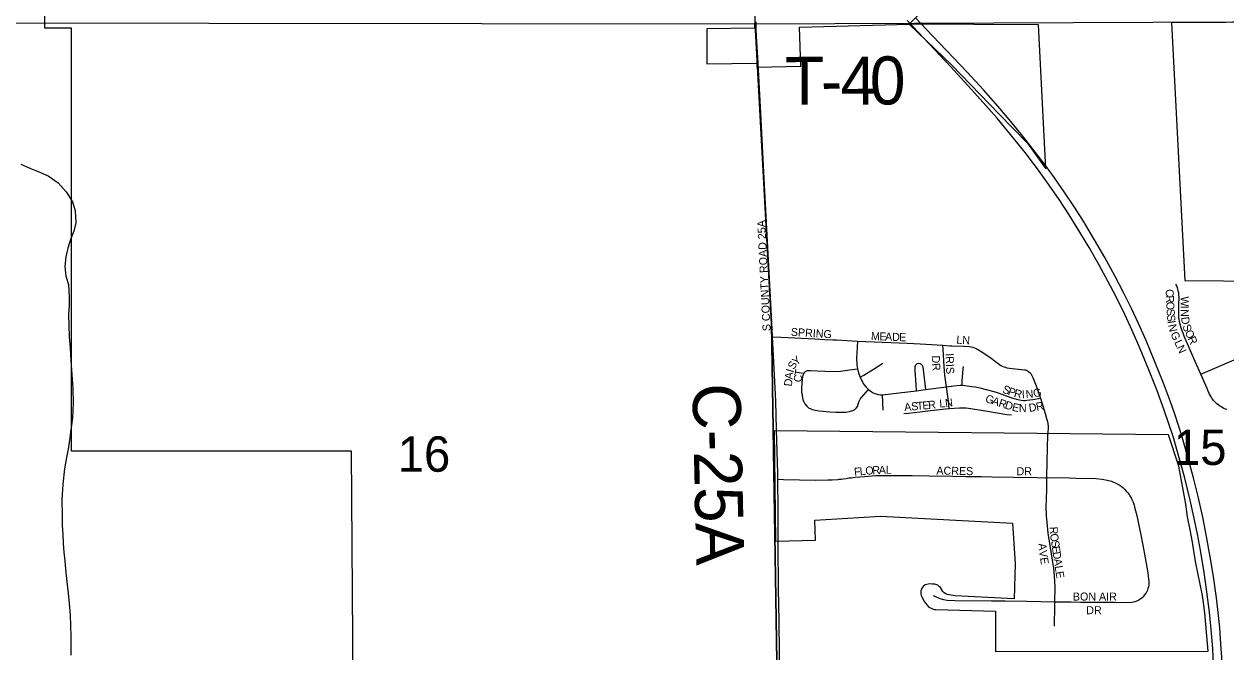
# Model space of a CAD drawing. Extents: x 0 to 680, y 0 to 440.
# Drawn here: x 474.22 to 499.3, y 246.29 to 259.39 of the extents above; entities that cross this region are included whole.
import ezdxf

# ---------------------------------------------------------------- set-up
doc = ezdxf.new("R2010")
doc.units = 0
for name, color, linetype in [('GM_X_City_Street', 7, 'Continuous'), ('GM_X_City_Street_Text', 7, 'Continuous'), ('GM_X_Corporation', 7, 'Continuous'), ('GM_X_County_Road', 7, 'Continuous'), ('GM_X_County_Road_Text', 7, 'Continuous'), ('GM_X_Interstate_Route', 7, 'Continuous'), ('GM_X_Minor_River', 7, 'Continuous'), ('GM_X_Section', 7, 'Continuous'), ('GM_X_Section_Text', 7, 'Continuous'), ('GM_X_Township_Road_Text', 7, 'Continuous'), ('GM_X_Township_Subdivision', 7, 'Continuous'), ('GM_X_Township_Subdivision_Text', 7, 'Continuous')]:
    doc.layers.add(name, color=color, linetype=linetype)

msp = doc.modelspace()

# ---------------------------------------------------------------- linework, layer by layer
at = {"layer": 'GM_X_City_Street'}
for points in [[(489.837, 252.862), (489.82, 253.168), (489.72, 255.118), (489.658, 256.301), (489.6, 257.393), (489.536, 258.572)], [(498.769, 252.09), (498.627, 252.416), (498.427, 252.881), (498.403, 252.94), (498.383, 252.992), (498.368, 253.035), (498.355, 253.075), (498.345, 253.11), (498.334, 253.15), (498.326, 253.192), (498.32, 253.233), (498.314, 253.27), (498.311, 253.314), (498.31, 253.361), (498.31, 253.412), (498.313, 253.536), (498.317, 253.693), (498.314, 253.741), (498.309, 253.78), (498.301, 253.819), (498.293, 253.856), (498.283, 253.888), (498.268, 253.927), (498.251, 253.963)], [(489.837, 252.862), (490.008, 252.859), (490.161, 252.854), (490.303, 252.847), (490.718, 252.825), (490.925, 252.811), (491.098, 252.804), (491.17, 252.801), (491.61, 252.772)], [(489.922, 250.933), (489.903, 251.521), (489.865, 252.334), (489.837, 252.862)], [(491.61, 252.772), (491.602, 252.645), (491.592, 252.421), (491.597, 252.29), (491.609, 252.199)], [(491.61, 252.772), (492.304, 252.748), (492.654, 252.735), (492.916, 252.717), (493.393, 252.689)], [(493.467, 251.825), (493.434, 252.063), (493.414, 252.247), (493.397, 252.605), (493.393, 252.689)], [(493.393, 252.689), (493.538, 252.68), (493.579, 252.679), (493.828, 252.674), (493.946, 252.666), (494.018, 252.65), (494.086, 252.622), (494.169, 252.573), (494.369, 252.439), (494.517, 252.327), (494.6, 252.27), (494.63, 252.255), (494.662, 252.241), (494.694, 252.23), (494.727, 252.222), (494.835, 252.203), (494.97, 252.189), (495.03, 252.186), (495.091, 252.179), (495.115, 252.174), (495.137, 252.168), (495.157, 252.158), (495.18, 252.143), (495.21, 252.117), (495.224, 252.102), (495.24, 252.075), (495.268, 252.018), (495.334, 251.845), (495.424, 251.587)], [(498.769, 252.09), (499.158, 252.253), (499.369, 252.343), (499.685, 252.479)], [(491.667, 252.022), (491.741, 252.066), (491.944, 252.193), (492.138, 252.313)], [(492.839, 251.739), (492.831, 251.866), (492.812, 252.172), (492.815, 252.249), (492.825, 252.28), (492.848, 252.303), (492.879, 252.314), (492.911, 252.312), (492.941, 252.298), (492.962, 252.274), (492.974, 252.243), (493.03, 251.768)], [(493.793, 251.854), (493.796, 251.944), (493.814, 252.195), (493.82, 252.25)], [(490.45, 251.688), (490.45, 251.795), (490.462, 251.979), (490.474, 252.063), (490.488, 252.1), (490.511, 252.131), (490.534, 252.148), (490.55, 252.155), (490.569, 252.16), (490.632, 252.162), (490.925, 252.147), (491.112, 252.142), (491.255, 252.151), (491.498, 252.184), (491.609, 252.199)], [(491.609, 252.199), (491.617, 252.16), (491.638, 252.096), (491.667, 252.022)], [(491.667, 252.022), (491.693, 251.965), (491.713, 251.925), (491.73, 251.895), (491.752, 251.862), (491.788, 251.815), (491.839, 251.766)], [(499.313, 251.347), (499.286, 251.358), (499.251, 251.374), (499.216, 251.392), (499.188, 251.409), (499.158, 251.428), (499.134, 251.447), (499.105, 251.469), (499.081, 251.491), (499.057, 251.516), (499.039, 251.538), (499.021, 251.56), (499.002, 251.587), (498.984, 251.616), (498.964, 251.65), (498.946, 251.684), (498.924, 251.729), (498.9, 251.785), (498.769, 252.09)], [(490.45, 251.688), (490.454, 251.644), (490.462, 251.594), (490.47, 251.559), (490.483, 251.523), (490.512, 251.468), (490.551, 251.419), (490.59, 251.387), (490.636, 251.366), (490.673, 251.352), (490.729, 251.337), (490.813, 251.322), (491.03, 251.298), (491.159, 251.293), (491.366, 251.296), (491.44, 251.307), (491.51, 251.328), (491.555, 251.353), (491.585, 251.379), (491.608, 251.412), (491.626, 251.459), (491.646, 251.523), (491.665, 251.565), (491.693, 251.603), (491.839, 251.766)], [(491.839, 251.766), (491.895, 251.726), (491.939, 251.7), (491.974, 251.684), (492, 251.674), (492.04, 251.664), (492.086, 251.659), (492.131, 251.656)], [(492.131, 251.656), (492.532, 251.703), (492.839, 251.739)], [(492.839, 251.739), (493.03, 251.768)], [(493.03, 251.768), (493.467, 251.825)], [(493.467, 251.825), (493.621, 251.845), (493.752, 251.856), (493.793, 251.854)], [(493.523, 251.371), (493.506, 251.533), (493.497, 251.62), (493.467, 251.825)], [(493.793, 251.854), (493.85, 251.85), (493.996, 251.832), (494.069, 251.82), (494.162, 251.799), (494.297, 251.766), (494.454, 251.722), (494.522, 251.703), (494.621, 251.67), (494.713, 251.638), (494.852, 251.588), (494.956, 251.555), (495.023, 251.542), (495.075, 251.537), (495.109, 251.538), (495.141, 251.542), (495.264, 251.559), (495.424, 251.587)], [(492.147, 251.339), (492.131, 251.656)], [(495.424, 251.587), (495.452, 251.495), (495.525, 251.269), (495.554, 251.165), (495.57, 251.101), (495.579, 251.049), (495.584, 250.999), (495.579, 250.836)], [(492.575, 251.263), (492.673, 251.271), (492.911, 251.299), (493.129, 251.326), (493.509, 251.37), (493.523, 251.371)], [(493.523, 251.371), (493.74, 251.386), (493.873, 251.384), (494.015, 251.367), (494.318, 251.314), (494.726, 251.243), (494.821, 251.236)], [(490.003, 243.711), (490.003, 243.935), (489.987, 245.238), (489.98, 246.289), (489.973, 246.935), (489.963, 247.614), (489.958, 248.547)]]:
    msp.add_lwpolyline(points, dxfattribs=at)
at = {"layer": 'GM_X_Corporation'}
for points in [[(481.118, 241.691), (481.055, 250.48), (475.217, 250.48), (475.216, 259.303), (474.655, 259.303), (474.655, 261.138), (474.551, 261.138), (474.551, 261.872), (474.184, 261.872)], [(489.496, 260.373), (489.458, 259.301), (488.464, 259.286), (488.464, 258.56), (489.507, 258.575), (489.51, 258.492), (490.429, 258.511), (490.397, 259.325), (492.69, 259.383), (492.991, 259.695)], [(502.694, 259.441), (498.159, 259.415), (498.441, 254.039), (503.27, 254.001)]]:
    msp.add_lwpolyline(points, dxfattribs=at)
for points in [[(492.69, 259.383), (493.577, 258.528), (494.561, 257.519), (495.158, 256.906), (495.541, 256.372), (495.384, 259.371)], [(489.872, 250.903), (489.897, 248.605), (490.732, 248.624), (490.722, 249.041), (491.638, 249.094), (492.092, 249.122), (494.842, 248.977), (494.901, 248.138), (494.875, 247.398), (493.648, 247.462), (493.481, 247.492), (493.449, 247.502), (493.416, 247.524), (493.388, 247.554), (493.338, 247.635), (493.314, 247.661), (493.282, 247.685), (493.22, 247.704), (493.164, 247.71), (493.124, 247.713), (493.083, 247.71), (493.021, 247.691), (492.98, 247.66), (492.958, 247.629), (492.941, 247.595), (492.934, 247.56), (492.931, 247.515), (492.94, 247.473), (492.959, 247.432), (493.006, 247.342), (493.031, 247.308), (493.099, 247.23), (493.207, 247.181), (493.241, 247.18), (494.486, 247.141), (494.486, 246.305), (498.922, 246.307), (498.855, 247.107), (498.804, 247.469), (498.663, 248.18), (498.596, 248.582), (498.552, 248.839), (498.492, 249.113), (498.455, 249.374), (498.315, 250.17), (498.1, 250.822)]]:
    msp.add_lwpolyline(points, close=True, dxfattribs=at)
at = {"layer": 'GM_X_County_Road'}
for points in [[(489.536, 258.572), (489.517, 258.911), (489.505, 259.127), (489.498, 259.298), (489.498, 259.365), (489.498, 259.435)], [(489.946, 249.896), (489.945, 250.021), (489.922, 250.933)], [(489.958, 248.547), (489.953, 249.249), (489.946, 249.896)]]:
    msp.add_lwpolyline(points, dxfattribs=at)
at = {"layer": 'GM_X_Interstate_Route'}
for points in [[(496.342, 255.24), (496.133, 255.567), (495.922, 255.886), (495.716, 256.182), (495.536, 256.43), (495.325, 256.708), (495.028, 257.087), (494.739, 257.443), (494.498, 257.726), (494.236, 258.019), (493.894, 258.388), (493.184, 259.133), (492.811, 259.528)], [(499.057, 245.417), (499.021, 246.364), (498.984, 246.764), (498.949, 247.125), (498.896, 247.549), (498.839, 247.951), (498.763, 248.416), (498.701, 248.75), (498.64, 249.051), (498.549, 249.458), (498.438, 249.916), (498.35, 250.244), (498.194, 250.787), (498.006, 251.337), (497.851, 251.759), (497.689, 252.178), (497.509, 252.614), (497.341, 252.995), (497.183, 253.333), (497.004, 253.698), (496.833, 254.029), (496.645, 254.376), (496.442, 254.728), (496.25, 255.047), (496.024, 255.41), (495.814, 255.731), (495.609, 256.03), (495.366, 256.368), (495.108, 256.709), (494.526, 257.423), (494.053, 257.956), (493.556, 258.496), (492.643, 259.46)], [(498.382, 250.782), (498.228, 251.252), (498.138, 251.511), (497.992, 251.899), (497.814, 252.346), (497.628, 252.79), (497.474, 253.14), (497.325, 253.456), (497.164, 253.779), (496.977, 254.137), (496.767, 254.521), (496.554, 254.89), (496.35, 255.226), (496.342, 255.24)], [(499.197, 246.357), (499.165, 246.795), (499.14, 247.056), (499.097, 247.425), (499.034, 247.869), (498.969, 248.279), (498.893, 248.699), (498.811, 249.106), (498.715, 249.533), (498.618, 249.925), (498.53, 250.252), (498.382, 250.782)], [(499.251, 215.048), (499.251, 215.074), (499.251, 217.418), (499.248, 220.255), (499.248, 224.759), (499.245, 229.732), (499.245, 230.699), (499.235, 234.233), (499.236, 234.641), (499.237, 236.207), (499.231, 238.398), (499.236, 241.137), (499.239, 243.03), (499.243, 244.793), (499.238, 245.307), (499.227, 245.734), (499.207, 246.182), (499.197, 246.357)]]:
    msp.add_lwpolyline(points, dxfattribs=at)
at = {"layer": 'GM_X_Minor_River'}
msp.add_lwpolyline([(474.156, 256.468), (474.348, 256.385), (474.521, 256.316), (474.727, 256.22), (474.933, 256.077), (475.104, 255.888), (475.236, 255.679), (475.294, 255.491), (475.304, 255.244), (475.262, 255.07), (475.193, 254.897), (475.138, 254.717), (475.095, 254.537), (475.073, 254.33), (475.097, 254.129), (475.149, 253.955), (475.166, 253.694), (475.164, 253.52), (475.155, 253.333), (475.159, 253.099), (475.169, 252.864), (475.187, 252.63), (475.197, 252.369), (475.22, 252.081), (475.243, 251.787), (475.247, 251.479), (475.236, 251.178), (475.2, 250.924), (475.171, 250.711), (475.142, 250.524), (475.113, 250.35), (475.07, 250.11), (475.033, 249.796), (475.016, 249.475), (475.019, 249.141), (475.023, 248.934), (475.034, 248.746), (475.038, 248.552), (475.056, 248.371), (475.074, 248.197), (475.086, 248.017), (475.116, 247.755), (475.147, 247.521), (475.164, 247.307), (475.188, 247.059), (475.192, 246.838), (475.203, 246.617), (475.201, 246.437), (475.198, 246.223)], dxfattribs=at)
at = {"layer": 'GM_X_Section'}
for points in [[(489.476, 259.394), (489.813, 253.134), (489.987, 242.13), (472.319, 241.773), (472.369, 259.414)], [(507.727, 259.473), (507.628, 241.733), (499.118, 242.119), (489.987, 242.13), (489.813, 253.134), (489.476, 259.394)]]:
    msp.add_lwpolyline(points, close=True, dxfattribs=at)
at = {"layer": 'GM_X_Township_Subdivision'}
for points in [[(495.559, 249.928), (495.564, 250.276), (495.57, 250.536), (495.579, 250.836)], [(489.946, 249.896), (490.064, 249.893), (490.731, 249.876), (490.988, 249.881), (491.084, 249.886), (491.206, 249.893), (491.228, 249.895), (491.266, 249.9), (491.309, 249.905), (491.371, 249.914), (491.429, 249.922), (491.482, 249.928), (491.563, 249.938), (491.753, 249.955), (491.837, 249.962), (491.995, 249.97), (492.105, 249.972), (492.321, 249.971), (492.747, 249.972), (493.107, 249.968), (493.599, 249.956), (493.871, 249.954), (493.97, 249.953), (494.188, 249.949), (494.418, 249.947), (494.866, 249.936), (495.347, 249.93), (495.53, 249.928), (495.559, 249.928)], [(495.729, 247.341), (495.73, 247.642), (495.72, 247.882), (495.705, 248.035), (495.657, 248.337), (495.587, 248.769), (495.557, 249.067), (495.552, 249.123), (495.546, 249.34), (495.549, 249.455), (495.557, 249.717), (495.558, 249.859), (495.559, 249.928)], [(495.559, 249.928), (495.716, 249.929), (496.033, 249.923), (496.164, 249.919), (496.579, 249.909), (496.711, 249.898), (496.821, 249.879), (496.907, 249.855), (496.999, 249.816), (497.068, 249.776), (497.107, 249.748), (497.142, 249.72), (497.178, 249.688), (497.214, 249.65), (497.247, 249.612), (497.274, 249.574), (497.292, 249.548), (497.322, 249.496), (497.333, 249.476), (497.348, 249.443), (497.359, 249.415), (497.38, 249.352), (497.398, 249.286), (497.434, 249.139), (497.475, 248.931), (497.51, 248.774), (497.561, 248.522), (497.612, 248.254), (497.648, 248.059), (497.667, 247.94), (497.676, 247.871), (497.68, 247.821), (497.684, 247.757), (497.684, 247.694), (497.678, 247.651), (497.669, 247.614), (497.65, 247.561)], [(493.187, 247.469), (493.328, 247.407), (493.403, 247.385), (493.48, 247.373), (493.645, 247.367), (494.404, 247.36)], [(495.729, 247.341), (496.064, 247.337), (496.26, 247.334), (496.796, 247.33), (496.97, 247.329), (497.223, 247.325), (497.334, 247.332), (497.401, 247.345), (497.455, 247.365), (497.502, 247.393), (497.549, 247.427), (497.579, 247.457), (497.603, 247.487), (497.63, 247.522), (497.65, 247.561)], [(494.404, 247.36), (494.432, 247.359), (494.605, 247.357), (494.69, 247.357)], [(494.69, 247.357), (495.136, 247.349), (495.729, 247.341)], [(495.722, 246.832), (495.728, 247.259), (495.729, 247.341)]]:
    msp.add_lwpolyline(points, dxfattribs=at)

# ---------------------------------------------------------------- texts
at = {"layer": 'GM_X_City_Street_Text'}
for s, height, rotation, p in [('S COUNTY ROAD 25A', 0.16689, 92.883, (489.799, 252.987)), ('C', 0.167, 272.7945, (498.035, 253.857)), ('R', 0.167, 272.8081, (498.041, 253.725)), ('O', 0.167, 272.9019, (498.048, 253.593)), ('W', 0.167, 270.4539, (498.351, 253.708)), ('I', 0.167, 270.437, (498.353, 253.517)), ('S', 0.167, 273.7803, (498.056, 253.443)), ('S', 0.167, 275.2323, (498.064, 253.321)), ('N', 0.167, 270.4545, (498.353, 253.443)), ('D', 0.167, 278.8202, (498.357, 253.27)), ('SPRING', 0.1669, 356.4925, (490.215, 252.887)), ('I', 0.167, 279.3977, (498.076, 253.191)), ('N', 0.167, 281.6422, (498.089, 253.112)), ('G', 0.167, 294.9637, (498.132, 252.928)), ('S', 0.167, 288.473, (498.386, 253.095)), ('O', 0.167, 295.1802, (498.432, 252.964)), ('M', 0.167, 357.8506, (491.888, 252.799)), ('E', 0.167, 357.8415, (492.064, 252.793)), ('A', 0.167, 357.8424, (492.182, 252.788)), ('D', 0.167, 357.8535, (492.329, 252.783)), ('E', 0.167, 357.8415, (492.475, 252.777)), ('L', 0.167, 355.4609, (493.667, 252.726)), ('N', 0.167, 358.1706, (493.793, 252.716)), ('L', 0.167, 294.5367, (498.213, 252.755)), ('R', 0.167, 294.4359, (498.494, 252.831)), ('Y', 0.167, 39.4278, (490.334, 252.26)), ('IRIS', 0.1669, 272.2013, (493.446, 252.52)), ('N', 0.167, 294.4729, (498.261, 252.648)), ('S', 0.167, 59.7298, (490.285, 252.17)), ('D', 0.167, 270.2186, (493.162, 252.474)), ('R', 0.167, 275.9335, (493.163, 252.309)), ('D', 0.167, 84.3525, (490.24, 251.826)), ('A', 0.167, 84.3525, (490.254, 251.972)), ('I', 0.167, 72.7816, (490.267, 252.109)), ('C', 0.167, 81.5197, (490.438, 251.908)), ('T', 0.167, 79.6438, (490.457, 252.037)), ('S', 0.167, 337.605, (494.617, 251.71)), ('P', 0.167, 340.2765, (494.734, 251.662)), ('R', 0.167, 346.4363, (494.863, 251.617)), ('I', 0.167, 1.8864, (495.04, 251.581)), ('N', 0.167, 5.4829, (495.125, 251.584)), ('G', 0.167, 11.3063, (495.289, 251.601)), ('A', 0.167, 4.7491, (492.59, 251.316)), ('S', 0.167, 4.7691, (492.736, 251.328)), ('T', 0.167, 4.7319, (492.853, 251.338)), ('E', 0.167, 4.7691, (492.97, 251.348)), ('R', 0.167, 6.7104, (493.093, 251.358)), ('L', 0.167, 5.0881, (493.324, 251.389)), ('N', 0.167, 6.6489, (493.446, 251.4)), ('G', 0.167, 341.5167, (494.261, 251.511)), ('A', 0.167, 341.5167, (494.4, 251.465)), ('R', 0.167, 341.5755, (494.54, 251.418)), ('D', 0.167, 343.0182, (494.67, 251.375)), ('E', 0.167, 346.2711, (494.82, 251.329)), ('D', 0.167, 8.1226, (495.194, 251.299)), ('R', 0.167, 11.5544, (495.35, 251.321)), ('N', 0.167, 359.2945, (494.975, 251.296))]:
    msp.add_text(s, height=height, rotation=rotation, dxfattribs=at).set_placement(p)
at = {"layer": 'GM_X_County_Road_Text'}
msp.add_text('C-25A', height=1.0014, rotation=271.2667, dxfattribs=at).set_placement((488.165, 251.886))
at = {"layer": 'GM_X_Section_Text'}
for s, p in [('16', (482.018, 250.052)), ('15', (498.21, 250.193))]:
    msp.add_text(s, height=0.7377, rotation=0, dxfattribs=at).set_placement(p)
at = {"layer": 'GM_X_Township_Road_Text'}
for s, rotation, p in [('T', 0.3831, (490.102, 257.702)), ('4', 0.1604, (491.257, 257.709)), ('0', 0.1604, (491.868, 257.711)), ('-', 0.3188, (490.85, 257.707))]:
    msp.add_text(s, height=1.001, rotation=rotation, dxfattribs=at).set_placement(p)
at = {"layer": 'GM_X_Township_Subdivision_Text'}
for s, height, rotation, p in [('F', 0.167, 5.6644, (491.546, 249.965)), ('L', 0.167, 5.6644, (491.663, 249.976)), ('O', 0.167, 4.2009, (491.779, 249.988)), ('R', 0.167, 2.9885, (491.924, 249.998)), ('A', 0.167, 1.3769, (492.055, 250.005)), ('L', 0.167, 0.0546, (492.201, 250.009)), ('ACRES', 0.1669, 358.9332, (493.254, 249.994)), ('DR', 0.1669, 0, (494.927, 249.979)), ('R', 0.167, 271.6761, (495.619, 248.904)), ('O', 0.167, 277.61, (495.625, 248.753)), ('A', 0.167, 276.7916, (495.378, 248.552)), ('S', 0.167, 278.4397, (495.645, 248.605)), ('E', 0.167, 278.4397, (495.662, 248.489)), ('V', 0.167, 277.7469, (495.396, 248.404)), ('E', 0.167, 279.0541, (495.416, 248.254)), ('D', 0.167, 278.4316, (495.679, 248.373)), ('A', 0.167, 278.4447, (495.701, 248.227)), ('L', 0.167, 278.447, (495.722, 248.082)), ('E', 0.167, 279.2807, (495.74, 247.963)), ('BON AIR', 0.1669, 0, (496.102, 247.365)), ('DR', 0.1669, 0, (496.381, 247.081))]:
    msp.add_text(s, height=height, rotation=rotation, dxfattribs=at).set_placement(p)

doc.saveas('drawing.dxf')
